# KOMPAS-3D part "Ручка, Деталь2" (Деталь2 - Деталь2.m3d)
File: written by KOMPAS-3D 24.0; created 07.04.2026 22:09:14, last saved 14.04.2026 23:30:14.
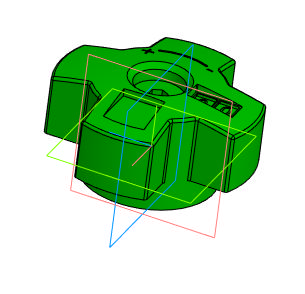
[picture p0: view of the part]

Document properties: Автор: tyuri; Полное имя файла: D:\Аутсорс\VB0000P-T Клапан балансировочный статический DN.ru\DN15\Исходные файлы\Деталь2 - Деталь2.m3d

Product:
- Body: Твердое тело1  | qty 1
    Масса: 0.541971
- Part/product: Ручка  | designation Деталь2
    Масса: 0.541971
    additional columns: Типовые

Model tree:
1. Твердое тело1  (labels: Твердое тело1)

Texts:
  Деталь2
